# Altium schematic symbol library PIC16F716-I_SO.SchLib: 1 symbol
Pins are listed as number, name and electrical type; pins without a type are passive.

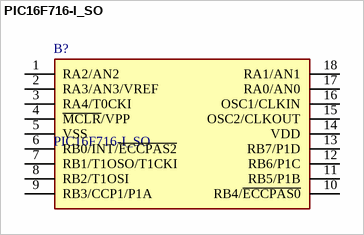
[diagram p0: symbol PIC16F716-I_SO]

## PIC16F716-I_SO
designator B?
Micro 16b, 3.5 KB Flash, PIC16F716-I/SO; Manufacturer_Name: Microchip; Geometry.Height: 2.65mm
footprint SOIC127P1030X265-18N
pins: 1 RA2/AN2, 2 RA3/AN3/VREF, 3 RA4/T0CKI, 4 ~{MCLR}/VPP, 5 VSS, 6 RB0/INT/~{ECCPAS2}, 7 RB1/T1OSO/T1CKI, 8 RB2/T1OSI, 9 RB3/CCP1/P1A, 10 RB4/~{ECCPAS0}, 11 RB5/P1B, 12 RB6/P1C, 13 RB7/P1D, 14 VDD, 15 OSC2/CLKOUT, 16 OSC1/CLKIN, 17 RA0/AN0, 18 RA1/AN1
